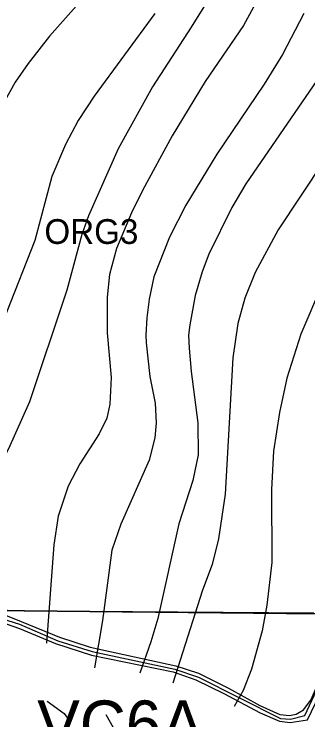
# Model space of a CAD drawing. Extents: x -1900516 to -575031, y -3809306 to -1157387.
# Drawn here: x -577986 to -577832, y -1161326 to -1160955.8 of the extents above; entities that cross this region are included whole.
import ezdxf

# ---------------------------------------------------------------- set-up
doc = ezdxf.new("R2010")
doc.units = 0
for name, color, linetype in [('01_OBVOD PÚ', 7, 'Continuous'), ('01_PRVKY PRŮZKUMU', 7, 'Continuous'), ('01_SPRÁV_HRANICE', 7, 'Continuous'), ('01_VRSTEVNICE', 7, 'Continuous'), ('02_KULTURY STAV', 7, 'Continuous'), ('03_PC_POPIS_STAV', 7, 'Continuous'), ('03_PC_STAV', 7, 'Continuous'), ('04_ZPF_OP_ORGAN', 7, 'Continuous')]:
    doc.layers.add(name, color=color, linetype=linetype)

msp = doc.modelspace()

# ---------------------------------------------------------------- linework, layer by layer
at = {"layer": '01_OBVOD PÚ'}
msp.add_lwpolyline([(-577828.91, -1161270.07), (-577971.47, -1161268.93), (-577998.69, -1161268.51)], dxfattribs=at)
at = {"layer": '01_PRVKY PRŮZKUMU'}
for points in [[(-578011.27, -1161268.31), (-577983.21, -1161278), (-577964.25, -1161285.87), (-577945.5, -1161292.05), (-577902.54, -1161300.84), (-577890.68, -1161305.05), (-577876.08, -1161312.19), (-577857.04, -1161322.37), (-577846.83, -1161326.71), (-577841.28, -1161327.3), (-577832.28, -1161325.96), (-577825.93, -1161312.8), (-577816.68, -1161290.49), (-577815.06, -1161278.18), (-577812.35, -1161274.62), (-577808.15, -1161272.47), (-577804.94, -1161272.09)], [(-577997.05, -1161268.54), (-577982.2, -1161274.46), (-577962.24, -1161282.64), (-577946.06, -1161287.88), (-577901.2, -1161297.71), (-577889.29, -1161301.59), (-577873.65, -1161309.34), (-577857.29, -1161318.53), (-577846.72, -1161323.22), (-577841.59, -1161323.66), (-577838.09, -1161322.98), (-577834.26, -1161320.73), (-577830.53, -1161315.69), (-577826.82, -1161307.26), (-577819.9, -1161289.84), (-577819.16, -1161276.32), (-577817.23, -1161273.17), (-577815.39, -1161271.27)]]:
    msp.add_lwpolyline(points, dxfattribs=at)
at = {"layer": '01_SPRÁV_HRANICE'}
for p, q in [((-577971.47, -1161268.93), (-577998.69, -1161268.51)), ((-577828.91, -1161270.07), (-577971.47, -1161268.93))]:
    msp.add_line(p, q, dxfattribs=at)
at = {"layer": '01_VRSTEVNICE'}
for points in [[(-577778.31, -1160913.43), (-577809.77, -1160964.89), (-577864.58, -1161044.87), (-577871.85, -1161057.17), (-577883.88, -1161081.78), (-577887.51, -1161091.01), (-577891.01, -1161103.31), (-577893.81, -1161118.69), (-577894.56, -1161124.2), (-577894.22, -1161131), (-577893.25, -1161143.3), (-577889.75, -1161170.15), (-577889.61, -1161186.92), (-577892.27, -1161200.35), (-577899.68, -1161223.14), (-577910.72, -1161272.77), (-577914.36, -1161285.08), (-577920.09, -1161301.44)], [(-577706.53, -1160925.08), (-577711.62, -1160926.72), (-577720.01, -1160930.77), (-577738.88, -1160943.5), (-577755.94, -1160957.76), (-577776.36, -1160978.17), (-577798.73, -1161003.2), (-577823.76, -1161033.12), (-577847.67, -1161068.92), (-577859.69, -1161091.29), (-577865.14, -1161104.71), (-577868.78, -1161118.13), (-577871.3, -1161136.03), (-577875.35, -1161207.62), (-577878.84, -1161231.11), (-577882.2, -1161244.53), (-577887.23, -1161257.95), (-577902.75, -1161306.75)], [(-577875.21, -1160933.57), (-577893.11, -1160962.65), (-577913.38, -1160993.97), (-577931.42, -1161026.41), (-577947.08, -1161061.64), (-577950.57, -1161071.43), (-577958.4, -1161100.65), (-577959.1, -1161102.75), (-577977.98, -1161159.24), (-577988.88, -1161183.85), (-578003.15, -1161210.69), (-578005.94, -1161217.41), (-578007.06, -1161226.35), (-578003.84, -1161242.01), (-578003.01, -1161253.2), (-578004.12, -1161261.31), (-578007.06, -1161268.44)], [(-577856.33, -1160944.2), (-577865.84, -1160961.81), (-577885.84, -1160991.18), (-577903.17, -1161019.7), (-577918.69, -1161048.22), (-577924.43, -1161059.97), (-577932.26, -1161078.7), (-577936.03, -1161092.41), (-577937.29, -1161104.29), (-577937.15, -1161122.89), (-577935.19, -1161146.38), (-577935.89, -1161160.36), (-577937.43, -1161167.77), (-577941.34, -1161176.02), (-577951.55, -1161191.68), (-577957.7, -1161203.42), (-577962.88, -1161219.08), (-577965.11, -1161234.18), (-577969.03, -1161285.78)], [(-577952.11, -1160950.07), (-577967.35, -1160967.27), (-577978.68, -1160981.67), (-577985.39, -1160991.45), (-577994.9, -1161008.23), (-578002.87, -1161025.01), (-578012.93, -1161050.18), (-578023.98, -1161088.77), (-578032.09, -1161112.26), (-578040.06, -1161129.88), (-578044.39, -1161137.71), (-578054.32, -1161150.71), (-578069.28, -1161165.67), (-578075.85, -1161171.12), (-578095.15, -1161184.27), (-578103.4, -1161188.88), (-578112.77, -1161191.4), (-578129.54, -1161194.05), (-578135, -1161193.92)], [(-577912.26, -1160955.38), (-577944, -1160998.73), (-577952.39, -1161011.59), (-577959.1, -1161024.17), (-577966.23, -1161040.95), (-577975.04, -1161074.51), (-577990, -1161112.26), (-578001.05, -1161134.35), (-578013.63, -1161153.65), (-578028.45, -1161172.94), (-578044.25, -1161190.7), (-578061.73, -1161208.32), (-578075.29, -1161218.94), (-578086.48, -1161225.24), (-578098.22, -1161227.75), (-578117.8, -1161227.61), (-578127.73, -1161227.47)], [(-577834.1, -1160955.38), (-577845.29, -1160976.91), (-577854.94, -1160992.57), (-577879.68, -1161029.21), (-577895.9, -1161056.05), (-577904.57, -1161072.83), (-577912.68, -1161093.52), (-577915.2, -1161105.27), (-577916.46, -1161115.06), (-577916.96, -1161124.2), (-577916.74, -1161128.2), (-577914.78, -1161145.82), (-577911.98, -1161159.8), (-577911.56, -1161170.15), (-577912.26, -1161177.98), (-577915.2, -1161189.72), (-577930.02, -1161223.28), (-577934.77, -1161236.98), (-577939.67, -1161273.89), (-577943.86, -1161298.64)], [(-577754.42, -1161021.46), (-577794.11, -1161057.03), (-577803.76, -1161066.96), (-577815.51, -1161081.78), (-577824.32, -1161097.16), (-577835.64, -1161123.73), (-577843.05, -1161146.66), (-577846.96, -1161164.83), (-577849.96, -1161185.03), (-577851.02, -1161205.1), (-577850.88, -1161243.41), (-577853.54, -1161265.78), (-577856.05, -1161279.21), (-577861.65, -1161299.34), (-577865.98, -1161310.53), (-577870.73, -1161319.05)], [(-577968.61, -1161316.26), (-577959.66, -1161322.69), (-577957.98, -1161325.07), (-577957.7, -1161327.58)], [(-577937.99, -1161323.25), (-577930.16, -1161336.81)]]:
    msp.add_lwpolyline(points, dxfattribs=at)
at = {"layer": '02_KULTURY STAV'}
msp.add_lwpolyline([(-577828.91, -1161270.07), (-577971.47, -1161268.93), (-577998.69, -1161268.51), (-578000.36, -1161268.48), (-578001.92, -1161267.97), (-578021.83, -1161261.66), (-578043.57, -1161256.81), (-578065.55, -1161253.19), (-578076.22, -1161251.31), (-578091.94, -1161245.5), (-578102.4, -1161237.97), (-578115.13, -1161226.1), (-578126.5, -1161202.05), (-578129.86, -1161190.72), (-578133.43, -1161178.71), (-578136.22, -1161168.2), (-578139.33, -1161156.45), (-578143.07, -1161134.44), (-578157.13, -1161076.39), (-578158.38, -1161072.45), (-578173.16, -1161008.46), (-578189.9, -1160916.19)], dxfattribs=at)
at = {"layer": '03_PC_STAV'}
msp.add_lwpolyline([(-578108.55, -1161235.7), (-578076.67, -1161253.25), (-578043.68, -1161258.6), (-578022.35, -1161263.57), (-577983.16, -1161275.8), (-577963.04, -1161284.55), (-577945.1, -1161290.13), (-577901.81, -1161299.32), (-577889.42, -1161303.65), (-577846.4, -1161325.37), (-577841.17, -1161325.68), (-577833.59, -1161323.73), (-577811.84, -1161276.79), (-577808.96, -1161271.94), (-577801.31, -1161269.18)], dxfattribs=at)
at = {"layer": '04_ZPF_OP_ORGAN'}
for points in [[(-578183.52, -1160902.39), (-578166.54, -1161007.19), (-578149.81, -1161079.89), (-578148.02, -1161083.77), (-578132.13, -1161157.55), (-578122.54, -1161187.01), (-578115.04, -1161206.65), (-578110.81, -1161210.39), (-578107.64, -1161212.03), (-578105.43, -1161214.27), (-578103.13, -1161217.78), (-578101.92, -1161221.62), (-578101.65, -1161225.75), (-578103.1, -1161230.36), (-578105.66, -1161234.1), (-578075.84, -1161250.85), (-578043.2, -1161256.15), (-578021.12, -1161261.3), (-577997.98, -1161268.55), (-577826.04, -1161270.33)], [(-577826.04, -1161270.33), (-577997.98, -1161268.55), (-578021.12, -1161261.3), (-578043.2, -1161256.15), (-578075.84, -1161250.85), (-578105.66, -1161234.1), (-578103.1, -1161230.36), (-578101.65, -1161225.75), (-578101.92, -1161221.62), (-578103.13, -1161217.78), (-578105.43, -1161214.27), (-578107.64, -1161212.03), (-578110.81, -1161210.39), (-578115.04, -1161206.65), (-578122.54, -1161187.01), (-578132.13, -1161157.55), (-578148.02, -1161083.77), (-578149.81, -1161079.89), (-578166.54, -1161007.19), (-578183.52, -1160902.39)]]:
    msp.add_lwpolyline(points, dxfattribs=at)

# ---------------------------------------------------------------- texts
at = {"layer": '03_PC_POPIS_STAV'}
msp.add_text('VC6A', height=25, dxfattribs=at).set_placement((-577973.85, -1161340.84))
at = {"layer": '04_ZPF_OP_ORGAN'}
msp.add_text('ORG3', height=13, dxfattribs=at).set_placement((-577970.11, -1161076.32))

doc.saveas('drawing.dxf')
